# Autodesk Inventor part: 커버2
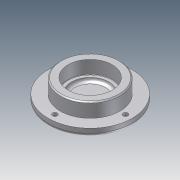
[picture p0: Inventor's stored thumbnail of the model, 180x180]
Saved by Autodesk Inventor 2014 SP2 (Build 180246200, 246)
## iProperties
Company: 한국ATC센터
Created: 2014-10
Part Number: 커버2
Document SubType Name: Modeling
Designer: KYOUNG IL JANG
Density: 1 g/cm^3
Mass: 44.7286 g
Surface Area: 161.165 cm^2
Volume: 44.7286 cm^3
Material: 일반
Appearance: 기본값
Author: KYOUNG IL JANG
Revision Number: 1
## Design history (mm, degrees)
sketch "스케치1"
  geometry: C1 r 38 at (0, 0); 1 further point
  constraints: 1 centre point, 1 coincident
  dimensions: "d0" = 76 diameter of C1
extrude "돌출1" new body sketch "스케치1" distance "d1" = 7; taper "d2" = 0 deg
sketch "스케치2"
  geometry: C1 r 27 at (0, 0); 1 further point
  constraints: 1 centre point, 1 coincident
  dimensions: "d3" = 54 diameter of C1
extrude "돌출2" join sketch "스케치2" distance "d4" = 13; taper "d5" = 0 deg
hole "구멍2" diameter "d20" = 34; stored, may be unused: countersink angle "d24" = 90 deg, drill point angle "d26" = 0 deg; dims "d18" = 10, "d19" = 10, "d21" = 6, "d22" = 40, "d23" = 12, "d25" = 3
fillet "모깎기2" dims "d34" = 3
fillet "모깎기1" dims "d27" = 0.3
chamfer "모따기1" distance "d28" = 1; stored, may be unused: second distance "d29" = 2, angle "d30" = 45 deg
sketch "스케치4" dims "d35" = 64
  geometry: 3 further points
  constraints: 2 horizontal alignment, 1 coincident, 2 other
hole "구멍3" sketch "스케치4" at (32, 0) diameter "d36" = 4.5; stored, may be unused: countersink angle "d40" = 90 deg, drill point angle "d42" = 118 deg; dims "d37" = 6, "d38" = 8, "d39" = 4.4, "d41" = 13
node "솔리드1"
pattern_circular "원형 패턴1" dims angle "d44" = 360 deg
